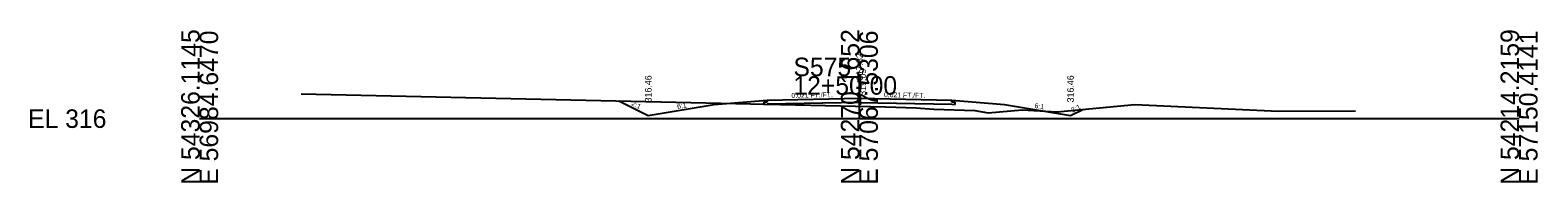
# Model space of a CAD drawing. Extents: x 10119 to 10347, y 94341 to 98867.
# Drawn here: x 10118.6 to 10347.2, y 96341.1 to 96364.2 of the extents above; entities that cross this region are included whole.
import ezdxf

# ---------------------------------------------------------------- set-up
doc = ezdxf.new("R2010")
doc.units = 0
for name, color, linetype in [('Level 10', 7, 'Continuous'), ('Level 11', 7, 'Continuous'), ('Level 12', 7, 'Continuous'), ('Level 32', 7, 'Continuous'), ('Level 33', 7, 'Continuous'), ('Level 59', 7, 'Continuous'), ('Level 6', 7, 'Continuous'), ('Level 60', 7, 'Continuous'), ('Level 63', 7, 'Continuous'), ('Level 7', 7, 'Continuous')]:
    doc.layers.add(name, color=color, linetype=linetype)

msp = doc.modelspace()

# ---------------------------------------------------------------- linework, layer by layer
at = {"layer": 'Level 11'}
for p, q in [((10230.31, 96353.32), (10229.81, 96353.31)), ((10229.81, 96353.31), (10229.81, 96352.97)), ((10229.81, 96352.97), (10230.31, 96352.98)), ((10230.31, 96353.61), (10230.31, 96353.32)), ((10258.31, 96353.32), (10258.31, 96353.61)), ((10258.81, 96353.31), (10258.31, 96353.32)), ((10258.31, 96352.98), (10258.81, 96352.97)), ((10258.81, 96352.97), (10258.81, 96353.31))]:
    msp.add_line(p, q, dxfattribs=at)
at = {"layer": 'Level 12'}
for q in [(10230.31, 96352.98), (10258.31, 96352.98)]:
    msp.add_line((10244.31, 96353.27), q, dxfattribs=at)
at = {"layer": 'Level 59'}
for p, q in [((10230.31, 96353.61), (10244.31, 96353.9)), ((10244.31, 96353.9), (10258.31, 96353.61))]:
    msp.add_line(p, q, dxfattribs=at)
at = {"layer": 'Level 6'}
for p, q in [((10222.31, 96352.94), (10230.31, 96353.61)), ((10258.31, 96353.61), (10266.31, 96352.94))]:
    msp.add_line(p, q, dxfattribs=at)
at = {"layer": 'Level 60'}
for p, q in [((10159.7, 96354.55), (10248.26, 96352.62)), ((10248.26, 96352.62), (10252.91, 96352.43)), ((10252.91, 96352.43), (10255.61, 96352.26)), ((10255.61, 96352.26), (10261.79, 96352.04)), ((10261.79, 96352.04), (10263.85, 96351.7)), ((10263.85, 96351.7), (10269, 96352.14)), ((10269, 96352.14), (10274.3, 96351.85)), ((10274.3, 96351.85), (10286.09, 96352.95)), ((10286.09, 96352.95), (10307.85, 96351.93)), ((10307.85, 96351.93), (10319.53, 96351.99))]:
    msp.add_line(p, q, dxfattribs=at)
at = {"layer": 'Level 63'}
for p, q in [((10244.31, 96350.81), (10244.31, 96357.23)), ((10144.31, 96350.81), (10244.31, 96350.81)), ((10244.31, 96350.81), (10344.31, 96350.81))]:
    msp.add_line(p, q, dxfattribs=at)
at = {"layer": 'Level 7'}
for p, q in [((10207.85, 96353.5), (10212.31, 96351.27)), ((10212.31, 96351.27), (10222.31, 96352.94)), ((10266.31, 96352.94), (10276.31, 96351.27)), ((10276.31, 96351.27), (10278.2, 96352.21))]:
    msp.add_line(p, q, dxfattribs=at)

# ---------------------------------------------------------------- texts
at = {"layer": 'Level 10'}
msp.add_text('317.82', height=1, rotation=90, dxfattribs=at).set_placement((10244.84, 96356.61))
at = {"layer": 'Level 32'}
for s, rotation, p in [('0.021 FT./FT.', 1.1916, (10234.02, 96353.93)), ('0.021 FT./FT.', 358.8084, (10248.03, 96354.07)), ('2:1', 333.435, (10209.69, 96352.87)), ('6:1', 9.4623, (10216.75, 96352.27)), ('6:1', 350.5377, (10270.83, 96352.44)), ('2:1', 26.5651, (10276.64, 96351.71))]:
    msp.add_text(s, height=0.75, rotation=rotation, dxfattribs=at).set_placement(p)
at = {"layer": 'Level 33'}
for p in [(10212.81, 96353.27), (10276.81, 96353.27)]:
    msp.add_text('316.46', height=1, rotation=90, dxfattribs=at).set_placement(p)
at = {"layer": 'Level 59'}
msp.add_text(' 319.09', height=1, rotation=90, dxfattribs=at).set_placement((10245.31, 96353.9))
at = {"layer": 'Level 63'}
for s, p in [('N 54326.1145', (10144.31, 96340.81)), ('E 56984.6470', (10147.11, 96340.81)), ('N 54270.1652', (10244.31, 96340.81)), ('E 57067.5306', (10247.11, 96340.81)), ('N 54214.2159', (10344.31, 96340.81)), ('E 57150.4141', (10347.11, 96340.81))]:
    msp.add_text(s, height=2.8, rotation=90, dxfattribs=at).set_placement(p)
for s, p in [('S575', (10234.32, 96357.23)), ('12+50.00', (10234.31, 96354.43)), ('EL 316', (10118.31, 96349.41))]:
    msp.add_text(s, height=2.8, dxfattribs=at).set_placement(p)

doc.saveas('drawing.dxf')
